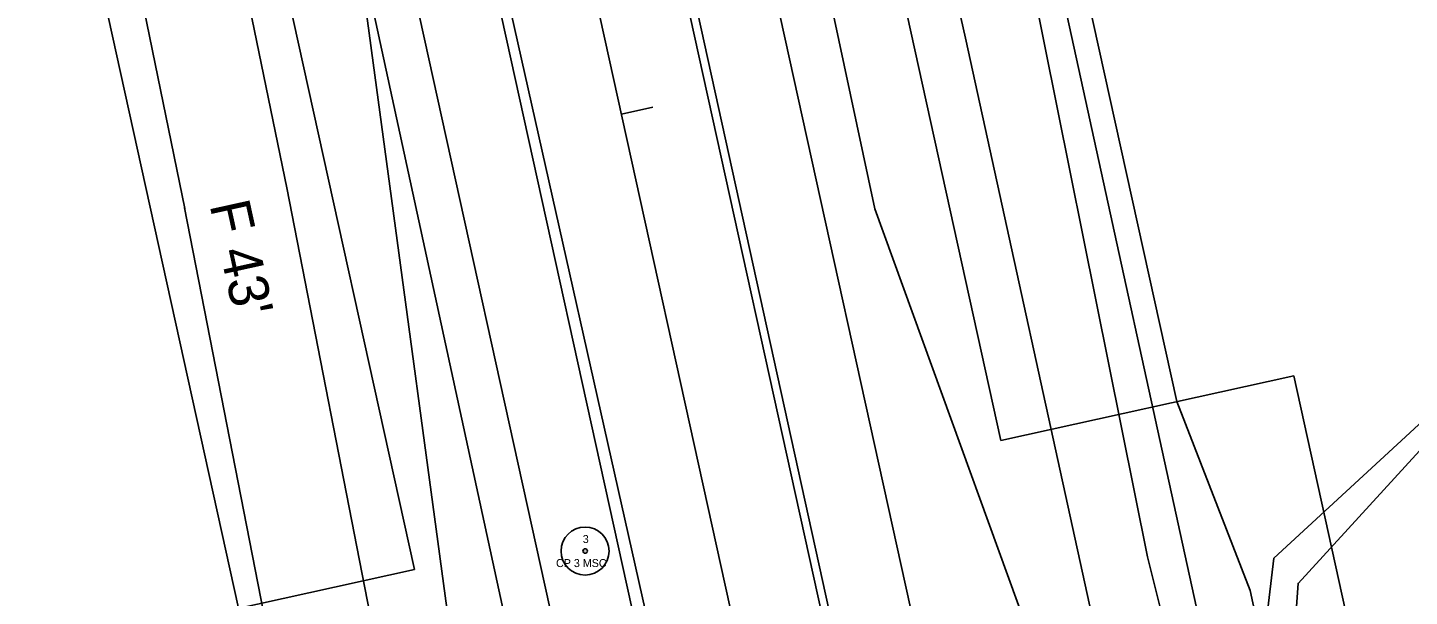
# Model space of a CAD drawing. Extents: x 2519952 to 2531965, y 848341 to 887632.
# Drawn here: x 2530852.7 to 2531025.3, y 852647.4 to 852718.4 of the extents above; entities that cross this region are included whole.
import ezdxf

# ---------------------------------------------------------------- set-up
doc = ezdxf.new("R2010")
doc.units = 0
for name, color, linetype in [('RD_EV_JW', 7, 'Continuous'), ('RD_EX_DV_Prop', 7, 'Continuous'), ('RD_EX_H2O', 7, 'Continuous'), ('RD_EX_Misc', 7, 'Continuous'), ('RD_EX_Road', 7, 'Continuous'), ('RD_EX_RW', 7, 'Continuous'), ('RD_EX_VEG', 7, 'Continuous'), ('RD_HC_Cl', 7, 'Continuous'), ('RD_HC_Data', 7, 'Continuous'), ('RD_HC_Data_Tic', 7, 'Continuous'), ('RD_HC_txCode', 7, 'Continuous'), ('RD_PD_BCA', 7, 'Continuous'), ('RD_PD_CstnLmt', 7, 'Continuous'), ('RD_PD_DR_ErosCtrl', 7, 'Continuous'), ('RD_PD_Final_TrvlWay', 7, 'Continuous'), ('RD_PD_GR', 7, 'Continuous'), ('RD_PD_RW', 7, 'Continuous'), ('RD_SMD_Locator', 7, 'Continuous')]:
    doc.layers.add(name, color=color, linetype=linetype)

msp = doc.modelspace()

# ---------------------------------------------------------------- linework, layer by layer
at = {"layer": 'RD_EV_JW'}
for points in [[(2530941.93, 852524.2), (2530921.34, 852539.21), (2530911.31, 852599.95), (2530891.36, 852747.65), (2530878.86, 852801.36), (2530855.69, 852888.8), (2530838.36, 852954.41), (2530821.58, 853001.04), (2530764.42, 853117.09), (2530719.97, 853083.34), (2530675.19, 853037.15)], [(2530941.93, 852524.2), (2530988.97, 852539.38), (2531002.68, 852568.81), (2530983.61, 852626.72), (2530958.57, 852695.74), (2530928.96, 852834.5), (2530911.44, 852907.05), (2530889.4, 853007.47), (2530879.48, 853052.19), (2530908.59, 853055.99), (2530938.06, 853061.93)]]:
    msp.add_lwpolyline(points, dxfattribs=at)
at = {"layer": 'RD_EX_DV_Prop'}
for p, q in [((2530858.55, 853192.44), (2530974.29, 852666.83)), ((2530851.48, 852875.81), (2530901.05, 852650.7)), ((2530974.29, 852666.83), (2531010.91, 852674.9)), ((2531010.91, 852674.9), (2531075.43, 852381.91)), ((2530901.05, 852650.7), (2530864.42, 852642.64))]:
    msp.add_line(p, q, dxfattribs=at)
at = {"layer": 'RD_EX_H2O'}
msp.add_lwpolyline([(2531245.62, 852555.32), (2531217.13, 852603.96), (2531237.99, 852642.9), (2531212.72, 852681.81), (2531164.02, 852716.47), (2531121.37, 852702), (2531085.6, 852695.19), (2531055.75, 852662.27), (2531031.08, 852670.41), (2531011.43, 852648.97), (2531007.69, 852596.79)], dxfattribs=at)
at = {"layer": 'RD_EX_Misc'}
msp.add_lwpolyline([(2531247.07, 852555.52), (2531218.06, 852604.32), (2531238.71, 852643.24), (2531220.29, 852673.34), (2531213.69, 852682.74), (2531164.29, 852718.15), (2531121, 852703.45), (2531084.9, 852696.42), (2531055.62, 852662.84), (2531030.72, 852672.68), (2531008.42, 852652.11), (2531002.15, 852599.45)], dxfattribs=at)
at = {"layer": 'RD_EX_Road'}
for p, q in [((2530952, 852644.96), (2530932.11, 852735.09)), ((2530931.08, 852640.35), (2530910.78, 852730.8))]:
    msp.add_line(p, q, dxfattribs=at)
at = {"layer": 'RD_EX_RW'}
for p, q in [((2530858.55, 853192.44), (2530974.29, 852666.83)), ((2530851.48, 852875.81), (2530901.05, 852650.7)), ((2530974.29, 852666.83), (2531010.92, 852674.89)), ((2531010.92, 852674.89), (2531075.43, 852381.91)), ((2530864.42, 852642.64), (2530901.05, 852650.7))]:
    msp.add_line(p, q, dxfattribs=at)
at = {"layer": 'RD_EX_VEG'}
for points in [[(2531006.39, 852597.18), (2530992.63, 852652.28), (2530913.79, 853044.4), (2530867.87, 853266.41)], [(2530930.57, 852548.23), (2530913.63, 852638.74), (2530872.38, 852829.12), (2530820.28, 852991.21)]]:
    msp.add_lwpolyline(points, dxfattribs=at)
at = {"layer": 'RD_HC_Cl'}
msp.add_line((2530821.93, 853184.38), (2531378.52, 850656.73), dxfattribs=at)
at = {"layer": 'RD_HC_Data'}
for radius in [3, 0.282]:
    msp.add_circle((2530922.37, 852653.01), radius, dxfattribs=at)
at = {"layer": 'RD_HC_Data_Tic'}
msp.add_line((2530926.92, 852707.59), (2530930.82, 852708.45), dxfattribs=at)
at = {"layer": 'RD_PD_BCA'}
for p, q in [((2530996.27, 852671.67), (2531005.46, 852648.09)), ((2531005.46, 852648.09), (2531010.81, 852623.64))]:
    msp.add_line(p, q, dxfattribs=at)
at = {"layer": 'RD_PD_CstnLmt'}
for p, q in [((2530947.36, 852814.49), (2530969.91, 852717.06)), ((2530865.02, 852796.36), (2530885.11, 852698.39)), ((2530969.91, 852717.06), (2530991.27, 852619.37)), ((2530885.11, 852698.39), (2530904.28, 852600.21))]:
    msp.add_line(p, q, dxfattribs=at)
at = {"layer": 'RD_PD_DR_ErosCtrl'}
for p, q in [((2530852.29, 852793.75), (2530872.38, 852695.78)), ((2530982.61, 852719.84), (2531003.97, 852622.15)), ((2530872.35, 852695.9), (2530891.52, 852597.72))]:
    msp.add_line(p, q, dxfattribs=at)
at = {"layer": 'RD_PD_Final_TrvlWay'}
for p, q in [((2530922.51, 852783.42), (2531196.7, 851538.25)), ((2530899.07, 852778.26), (2531173.26, 851533.09))]:
    msp.add_line(p, q, dxfattribs=at)
at = {"layer": 'RD_PD_GR'}
for p, q in [((2530922.87, 852828.3), (2530971.25, 852608.56)), ((2530928.28, 852599.1), (2530879.89, 852818.84))]:
    msp.add_line(p, q, dxfattribs=at)
at = {"layer": 'RD_PD_RW'}
for p, q in [((2530947.88, 852891.4), (2530996.27, 852671.67)), ((2530830.69, 852865.6), (2530879.07, 852645.86))]:
    msp.add_line(p, q, dxfattribs=at)
at = {"layer": 'RD_SMD_Locator'}
for centre in [(2530958.57, 852695.74), (2530922.37, 852653.01), (2530992.63, 852652.28), (2531008.42, 852652.11), (2531011.43, 852648.97)]:
    msp.add_circle(centre, 0.001, dxfattribs=at)

# ---------------------------------------------------------------- texts
at = {"layer": 'RD_HC_txCode'}
for s, p in [('3', (2530922.08, 852654.01)), ('CP 3 MSC', (2530918.74, 852651.01))]:
    msp.add_text(s, height=1, dxfattribs=at).set_placement(p)
at = {"layer": 'RD_PD_CstnLmt'}
msp.add_text("F 43'", height=5, rotation=282.4185, dxfattribs=at).set_placement((2530875.45, 852696.26))

doc.saveas('drawing.dxf')
